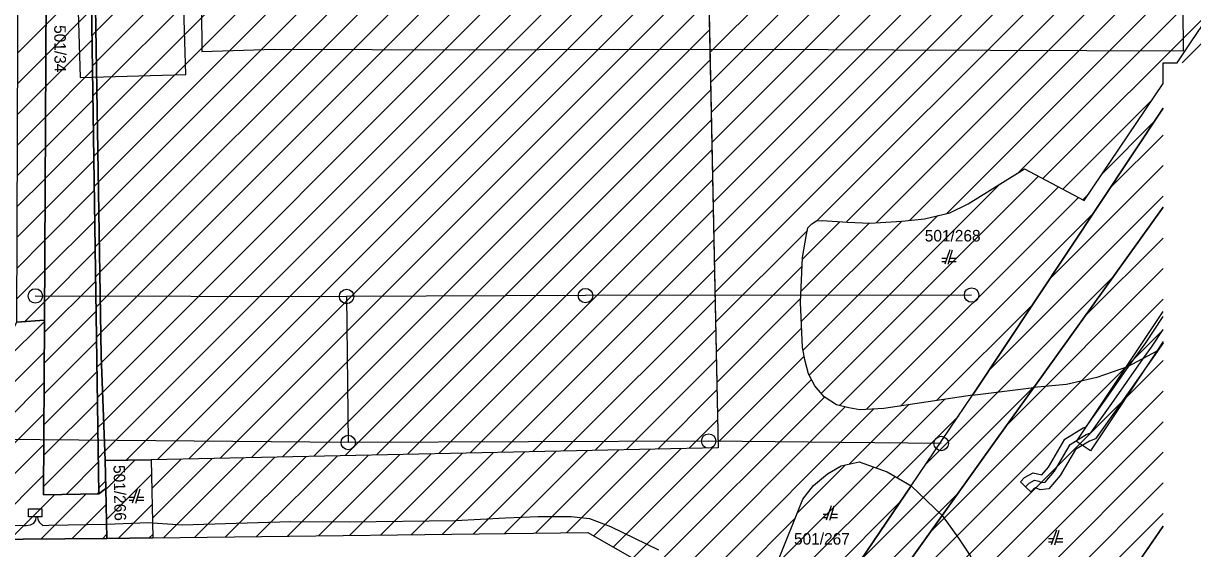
# Model space of a CAD drawing. Extents: x -264309 to -263505, y -1242443 to -1241763.
# Drawn here: x -263948.8 to -263786.7, y -1242319 to -1242246.2 of the extents above; entities that cross this region are included whole.
import ezdxf

# ---------------------------------------------------------------- set-up
doc = ezdxf.new("R2010")
doc.units = 0
for name, color, linetype in [('KFA_DAZDOVA_KANALIZACIA_retencna_nadrz', 7, 'Continuous'), ('KFA_DAZDOVA_KANALIZACIA_vetva_D', 7, 'Continuous'), ('KFA_DAZDOVA_KANALIZACIA_vetva_E', 7, 'Continuous'), ('KFA_SO_50-2_POZIARNY_VODOVOD_TRASA', 7, 'Continuous'), ('KN_2019_08_16', 7, 'Continuous'), ('KN_2019_08_16_KLADPAR', 7, 'Continuous'), ('KN_2019_08_16_ZAPPAR', 7, 'Continuous'), ('SRAFY_PARCELY', 7, 'Continuous')]:
    doc.layers.add(name, color=color, linetype=linetype)

msp = doc.modelspace()

# ---------------------------------------------------------------- linework, layer by layer
at = {"layer": 'KFA_DAZDOVA_KANALIZACIA_retencna_nadrz'}
msp.add_lwpolyline([(-263941.49, -1242235.46), (-263940.97, -1242253.75), (-263926.32, -1242253.31), (-263926.85, -1242235.04)], close=True, dxfattribs=at)
at = {"layer": 'KFA_DAZDOVA_KANALIZACIA_vetva_D'}
msp.add_lwpolyline([(-263821.59, -1242304.45), (-263853.82, -1242304.12), (-263903.79, -1242304.32), (-263951.83, -1242303.9), (-264004.17, -1242304.05), (-264044.82, -1242304.22), (-264095.21, -1242304.15), (-264105.62, -1242304.17)], dxfattribs=at)
for centre in [(-263853.82, -1242304.12), (-263903.79, -1242304.32), (-263821.59, -1242304.45)]:
    msp.add_circle(centre, 1, dxfattribs=at)
at = {"layer": 'KFA_DAZDOVA_KANALIZACIA_vetva_E'}
for p, q in [((-263947.17, -1242284.01), (-263904.01, -1242284.08)), ((-263904.01, -1242284.08), (-263903.79, -1242304.32))]:
    msp.add_line(p, q, dxfattribs=at)
msp.add_lwpolyline([(-263817.37, -1242283.88), (-263870.9, -1242283.96), (-263904.01, -1242284.08)], dxfattribs=at)
for centre in [(-263947.17, -1242284.01), (-263904.01, -1242284.08), (-263870.9, -1242283.96), (-263817.37, -1242283.88)]:
    msp.add_circle(centre, 1, dxfattribs=at)
at = {"layer": 'KFA_SO_50-2_POZIARNY_VODOVOD_TRASA'}
msp.add_lwpolyline([(-263924.93, -1242185.13), (-263924.15, -1242197.09), (-263924.3, -1242220.9), (-263924.1, -1242250.12), (-263913.99, -1242249.8), (-263886.91, -1242249.88), (-263867.71, -1242249.83), (-263837.26, -1242249.84), (-263828.16, -1242249.9), (-263787.99, -1242250.03), (-263788.2, -1242220.84), (-263788.2, -1242200.51), (-263788.09, -1242179.92), (-263788.06, -1242148.96), (-263787.92, -1242127.95), (-263787.95, -1242110.97), (-263788.13, -1242082.54), (-263828.43, -1242082.72), (-263836.78, -1242082.56), (-263867.31, -1242082.61), (-263886.71, -1242082.47), (-263924.08, -1242082.61), (-263924.64, -1242106.32), (-263924.48, -1242117.43)], close=True, dxfattribs=at)
at = {"layer": 'KN_2019_08_16'}
for p, q in [((-263795.99, -1242293.93), (-263790.83, -1242286.16)), ((-263795.99, -1242293.93), (-263790.83, -1242286.16)), ((-263790.83, -1242290.31), (-263791.71, -1242291.64)), ((-263790.83, -1242290.31), (-263791.71, -1242291.64)), ((-263791.71, -1242291.64), (-263800.9, -1242305.47)), ((-263791.71, -1242291.64), (-263800.9, -1242305.47)), ((-263802.81, -1242304.19), (-263795.99, -1242293.93)), ((-263802.81, -1242304.19), (-263795.99, -1242293.93)), ((-263800.9, -1242305.47), (-263802.81, -1242304.19)), ((-263800.9, -1242305.47), (-263802.81, -1242304.19))]:
    msp.add_line(p, q, dxfattribs=at)
for points in [[(-263790.83, -1242290.5), (-263791.59, -1242291.66), (-263797.1, -1242299.46), (-263800.21, -1242303.81), (-263801.03, -1242304.12), (-263802.98, -1242305.3), (-263805.07, -1242308.88), (-263806.66, -1242310.76), (-263807.87, -1242310.9), (-263808.52, -1242310.61), (-263808.8, -1242310.77), (-263809.16, -1242311.14), (-263809.88, -1242310.45), (-263810.6, -1242309.76), (-263810.02, -1242309.15), (-263808.82, -1242308.51), (-263807.62, -1242308.79), (-263806.71, -1242307.72), (-263804.46, -1242303.86), (-263801.91, -1242302.3), (-263801.47, -1242302.15), (-263798.74, -1242298.32), (-263795.58, -1242293.75), (-263793.23, -1242290.52), (-263790.83, -1242286.86)], [(-263809.88, -1242310.45), (-263809.41, -1242309.96), (-263808.67, -1242309.56), (-263808.06, -1242309.69), (-263807.69, -1242309.87), (-263807.17, -1242309.81), (-263805.89, -1242308.3), (-263803.72, -1242304.58), (-263801.47, -1242303.21), (-263800.84, -1242302.98), (-263797.92, -1242298.89), (-263793.53, -1242292.63), (-263792.41, -1242291.09), (-263790.83, -1242288.68)], [(-263954.68, -1242315.7), (-263948.7, -1242315.83), (-263948.46, -1242315.82), (-263947.86, -1242315.75), (-263947.37, -1242315.51), (-263947.08, -1242315.09), (-263947.04, -1242314.61)], [(-263946.86, -1242314.61), (-263946.83, -1242315.01), (-263946.58, -1242315.41), (-263946.15, -1242315.83), (-263945.29, -1242315.78), (-263937.31, -1242315.63), (-263931.52, -1242315.4), (-263930.92, -1242315.44), (-263926.77, -1242315.74), (-263919.34, -1242315.51), (-263911.76, -1242315.27), (-263903.58, -1242315.33), (-263888.93, -1242315.15), (-263882, -1242314.76), (-263877.47, -1242314.59), (-263872.88, -1242314.58), (-263870.34, -1242314.83), (-263867.42, -1242315.97), (-263860.78, -1242319.2)]]:
    msp.add_lwpolyline(points, dxfattribs=at)
msp.add_lwpolyline([(-263947.04, -1242314.61), (-263948.11, -1242314.61), (-263948.11, -1242313.51), (-263946.29, -1242313.51), (-263946.29, -1242314.61), (-263946.86, -1242314.61)], close=True, dxfattribs=at)
at = {"layer": 'KN_2019_08_16_KLADPAR'}
for p, q in [((-263786.91, -1242248.79), (-263758.42, -1242206.43)), ((-263788.88, -1242251.71), (-263786.91, -1242248.79)), ((-263801.77, -1242270.76), (-263790.83, -1242254.58)), ((-263790.83, -1242258), (-263817.23, -1242297.78)), ((-263817.83, -1242271.26), (-263810.05, -1242266.37)), ((-263810.05, -1242266.37), (-263801.77, -1242270.76)), ((-263823.91, -1242273.3), (-263820.38, -1242272.48)), ((-263820.38, -1242272.48), (-263817.83, -1242271.26)), ((-263840.06, -1242274.56), (-263839.51, -1242274)), ((-263839.51, -1242274), (-263838.86, -1242273.61)), ((-263838.86, -1242273.61), (-263838.09, -1242273.54)), ((-263838.09, -1242273.54), (-263834.58, -1242273.8)), ((-263834.58, -1242273.8), (-263831.48, -1242273.9)), ((-263831.48, -1242273.9), (-263827.03, -1242273.64)), ((-263827.03, -1242273.64), (-263823.91, -1242273.3)), ((-263840.83, -1242278.7), (-263840.26, -1242275.48)), ((-263840.26, -1242275.48), (-263840.06, -1242274.56)), ((-263841.11, -1242284.9), (-263840.83, -1242278.7)), ((-263820.82, -1242278.82), (-263821.5, -1242278.82)), ((-263820.4, -1242277.62), (-263821.1, -1242279.62)), ((-263820.6, -1242279.62), (-263820, -1242277.62)), ((-263819.5, -1242278.82), (-263820.36, -1242278.82)), ((-263821.5, -1242279.22), (-263820.96, -1242279.22)), ((-263820.48, -1242279.22), (-263819.5, -1242279.22)), ((-263840.8, -1242291.13), (-263841.11, -1242284.9)), ((-263840.43, -1242293.03), (-263840.8, -1242291.13)), ((-263839.99, -1242294.81), (-263840.43, -1242293.03)), ((-263839.09, -1242296.45), (-263839.99, -1242294.81)), ((-263837.8, -1242298.01), (-263839.09, -1242296.45)), ((-263836.1, -1242299.11), (-263837.8, -1242298.01)), ((-263817.23, -1242297.78), (-263829.54, -1242299.6)), ((-263834.37, -1242299.51), (-263836.1, -1242299.11)), ((-263832.88, -1242299.77), (-263834.37, -1242299.51)), ((-263829.54, -1242299.6), (-263832.88, -1242299.77)), ((-263933.04, -1242310.73), (-263933.74, -1242312.73)), ((-263933.24, -1242312.73), (-263932.64, -1242310.73)), ((-263933.46, -1242311.93), (-263934.14, -1242311.93)), ((-263934.14, -1242312.33), (-263933.6, -1242312.33)), ((-263933.12, -1242312.33), (-263932.14, -1242312.33)), ((-263932.14, -1242311.93), (-263933, -1242311.93)), ((-263837.26, -1242314.3), (-263837.94, -1242314.3)), ((-263836.84, -1242313.1), (-263837.54, -1242315.1)), ((-263837.04, -1242315.1), (-263836.44, -1242313.1)), ((-263835.94, -1242314.3), (-263836.8, -1242314.3)), ((-263837.94, -1242314.7), (-263837.4, -1242314.7)), ((-263836.92, -1242314.7), (-263835.94, -1242314.7)), ((-263796.96, -1242324.83), (-263790.83, -1242315.89)), ((-263806.04, -1242317.69), (-263806.72, -1242317.69)), ((-263805.62, -1242316.49), (-263806.32, -1242318.49)), ((-263805.82, -1242318.49), (-263805.22, -1242316.49)), ((-263804.72, -1242317.69), (-263805.58, -1242317.69)), ((-263806.72, -1242318.09), (-263806.18, -1242318.09)), ((-263805.7, -1242318.09), (-263804.72, -1242318.09))]:
    msp.add_line(p, q, dxfattribs=at)
for points in [[(-263945.92, -1242287.35), (-263949.74, -1242287.63), (-263949.41, -1242196.68), (-263949.38, -1242187.85), (-263949.49, -1242175.05), (-263949.55, -1242159.39), (-263950.14, -1242129.96), (-263950.48, -1242111.43), (-263955.8, -1242087.79), (-263956.24, -1242069.24), (-263949.96, -1242070.83), (-263947.13, -1242072.33), (-263942.68, -1242071.91), (-263941.47, -1242124.08), (-263944.59, -1242125.87), (-263946.11, -1242129.79), (-263945.51, -1242159.3), (-263945.41, -1242187.87)], [(-263945.92, -1242287.35), (-263945.41, -1242187.87), (-263945.51, -1242159.3), (-263946.11, -1242129.79), (-263944.59, -1242125.87), (-263941.47, -1242124.08), (-263940.13, -1242193.8), (-263938.35, -1242311.44), (-263946.05, -1242311.56)], [(-263939.79, -1242196.85), (-263933.6, -1242196.72), (-263889.52, -1242195.8), (-263854.81, -1242195.07), (-263852.5, -1242305.04), (-263931.11, -1242306.7), (-263937.48, -1242306.83), (-263938.02, -1242292.26), (-263938.87, -1242241.14), (-263939.37, -1242217.33)], [(-264045.86, -1242306.31), (-263951.37, -1242306.76), (-263951.29, -1242290.6), (-263949.74, -1242287.63), (-263945.92, -1242287.35), (-263946.05, -1242311.56), (-263938.35, -1242311.44), (-263937.4, -1242310.7), (-263937.27, -1242317.62), (-263989.58, -1242318.02), (-264012.87, -1242318.24), (-264024.87, -1242318.35), (-264045.81, -1242319.96), (-264048.82, -1242319.93), (-264044.28, -1242315.26), (-264044.13, -1242307.8)], [(-263937.27, -1242317.62), (-263937.4, -1242310.7), (-263937.48, -1242306.83), (-263931.11, -1242306.7), (-263930.87, -1242317.54)], [(-263843.11, -1242332.49), (-263836.94, -1242324.08), (-263844.32, -1242321.02), (-263840.75, -1242312.15), (-263839.31, -1242310.28), (-263837.34, -1242308.65), (-263835.46, -1242307.53), (-263832.97, -1242307.02), (-263829.09, -1242308.37), (-263825.74, -1242310.33), (-263842.23, -1242334.63), (-263842.59, -1242334.42)]]:
    msp.add_lwpolyline(points, close=True, dxfattribs=at)
for points in [[(-263942.54, -1242071.9), (-263941.18, -1242123.7), (-263940.74, -1242147.99), (-263940.34, -1242170.51), (-263939.79, -1242196.85), (-263939.37, -1242217.33), (-263938.87, -1242241.14), (-263938.02, -1242292.26), (-263937.48, -1242306.83), (-263937.4, -1242310.7), (-263938.35, -1242311.44), (-263940.13, -1242193.8), (-263941.47, -1242124.08), (-263942.68, -1242071.91)], [(-263915.82, -1242443.45), (-263899.7, -1242418.94), (-263895.05, -1242412.05), (-263870.81, -1242376.19), (-263864.8, -1242372.36), (-263866.24, -1242369.43), (-263842.59, -1242334.42), (-263842.23, -1242334.63), (-263825.74, -1242310.33), (-263817.23, -1242297.78), (-263790.83, -1242258)], [(-263889.11, -1242409.04), (-263871.85, -1242385.03), (-263844.47, -1242346.65), (-263821.45, -1242314.43), (-263813.84, -1242303.78), (-263808.74, -1242296.68), (-263790.83, -1242271.71)], [(-263790.83, -1242271.71), (-263808.74, -1242296.68), (-263813.84, -1242303.78), (-263821.45, -1242314.43), (-263844.47, -1242346.65), (-263871.85, -1242385.03), (-263889.11, -1242409.04)], [(-263790.83, -1242315.89), (-263796.96, -1242324.83), (-263799.93, -1242329.15), (-263801.69, -1242331.72)], [(-264069.25, -1242345.54), (-264061.99, -1242345.41), (-264045.98, -1242345.11), (-264024.64, -1242344.82), (-264024.87, -1242318.35), (-264012.87, -1242318.24), (-263989.58, -1242318.02), (-263937.27, -1242317.62), (-263930.87, -1242317.54), (-263870.55, -1242316.79)], [(-263870.55, -1242316.79), (-263843.11, -1242332.49), (-263842.59, -1242334.42), (-263866.24, -1242369.43), (-263870.81, -1242376.19), (-263895.05, -1242412.05), (-263899.7, -1242418.94), (-263928.14, -1242418.9), (-263933.06, -1242418.97), (-263955.09, -1242419.03), (-263978.33, -1242419.1), (-263997.04, -1242419.26), (-264025.44, -1242419.01), (-264068.96, -1242418.63), (-264069.2, -1242359.38), (-264069.25, -1242345.54)]]:
    msp.add_lwpolyline(points, dxfattribs=at)
at = {"layer": 'KN_2019_08_16_ZAPPAR'}
for p, q in [((-263817.23, -1242297.78), (-263808.74, -1242296.68)), ((-263825.74, -1242310.33), (-263821.45, -1242314.43))]:
    msp.add_line(p, q, dxfattribs=at)
for points in [[(-263790.83, -1242290.31), (-263791.71, -1242291.64), (-263795.77, -1242293.85), (-263800.03, -1242295.33), (-263804.21, -1242296.28), (-263808.74, -1242296.68)], [(-263821.45, -1242314.43), (-263819.18, -1242317.59), (-263817.51, -1242320.07), (-263816.33, -1242322.99), (-263815.74, -1242327.13)]]:
    msp.add_lwpolyline(points, dxfattribs=at)
at = {"layer": 'SRAFY_PARCELY'}
for p, q in [((-263853.65, -1242250.27), (-263766.58, -1242163.2)), ((-263853.56, -1242254.42), (-263766.58, -1242167.44)), ((-263853.48, -1242258.58), (-263766.58, -1242171.68)), ((-263853.39, -1242262.73), (-263766.58, -1242175.92)), ((-263853.3, -1242266.89), (-263766.58, -1242180.17)), ((-263853.21, -1242271.04), (-263766.58, -1242184.41)), ((-263853.13, -1242275.2), (-263766.58, -1242188.65)), ((-263853.04, -1242279.35), (-263766.58, -1242192.89)), ((-263938.77, -1242247.34), (-263887.18, -1242195.75)), ((-263938.7, -1242251.51), (-263882.84, -1242195.66)), ((-263938.63, -1242255.69), (-263878.51, -1242195.57)), ((-263938.56, -1242259.86), (-263874.18, -1242195.48)), ((-263938.49, -1242264.03), (-263869.84, -1242195.39)), ((-263938.42, -1242268.21), (-263865.51, -1242195.3)), ((-263938.35, -1242272.38), (-263861.18, -1242195.2)), ((-263938.28, -1242276.55), (-263856.84, -1242195.11)), ((-263854.81, -1242195.07), (-263852.5, -1242305.04)), ((-263938.21, -1242280.72), (-263854.76, -1242197.28)), ((-263852.95, -1242283.51), (-263766.58, -1242197.14)), ((-263838.81, -1242273.61), (-263766.36, -1242201.16)), ((-263938.14, -1242284.9), (-263854.68, -1242201.43)), ((-263834.75, -1242273.79), (-263763.81, -1242202.85)), ((-263938.07, -1242289.07), (-263854.59, -1242205.59)), ((-263830.56, -1242273.85), (-263761.26, -1242204.54)), ((-263826, -1242273.53), (-263758.71, -1242206.24)), ((-263786.91, -1242248.79), (-263758.42, -1242206.43)), ((-263937.98, -1242293.23), (-263854.5, -1242209.74)), ((-263937.83, -1242297.32), (-263854.41, -1242213.9)), ((-263937.68, -1242301.41), (-263854.33, -1242218.05)), ((-263820.81, -1242272.58), (-263766.14, -1242217.91)), ((-263937.53, -1242305.5), (-263854.24, -1242222.21)), ((-263934.56, -1242306.77), (-263854.15, -1242226.36)), ((-263930.23, -1242306.68), (-263854.07, -1242230.52)), ((-263810.88, -1242266.89), (-263774.86, -1242230.87)), ((-263925.89, -1242306.59), (-263853.98, -1242234.67)), ((-263921.56, -1242306.5), (-263853.89, -1242238.83)), ((-263945.71, -1242246.43), (-263939.43, -1242240.15)), ((-263917.22, -1242306.41), (-263853.8, -1242242.99)), ((-263945.73, -1242250.7), (-263939.37, -1242244.33)), ((-263807.48, -1242267.73), (-263783.57, -1242243.83)), ((-263949.6, -1242250.33), (-263945.71, -1242246.44)), ((-263939.31, -1242247.92), (-263938.77, -1242247.38)), ((-263912.89, -1242306.32), (-263853.72, -1242247.14)), ((-263788.16, -1242251.71), (-263783.68, -1242247.24)), ((-263945.75, -1242254.96), (-263939.3, -1242248.51)), ((-263788.88, -1242251.71), (-263786.91, -1242248.79)), ((-263949.62, -1242254.59), (-263945.73, -1242250.7)), ((-263908.56, -1242306.22), (-263853.63, -1242251.3)), ((-263945.78, -1242259.23), (-263939.24, -1242252.69)), ((-263939.25, -1242252.1), (-263938.7, -1242251.55)), ((-263790.83, -1242254.58), (-263790.83, -1242251.71)), ((-263790.83, -1242251.71), (-263788.88, -1242251.71)), ((-263801.77, -1242270.76), (-263790.83, -1242254.58)), ((-263949.64, -1242258.85), (-263945.75, -1242254.96)), ((-263939.18, -1242256.28), (-263938.63, -1242255.72)), ((-263904.22, -1242306.13), (-263853.54, -1242255.45)), ((-263945.8, -1242263.49), (-263939.18, -1242256.87)), ((-263804.71, -1242269.2), (-263792.38, -1242256.88)), ((-263949.65, -1242263.1), (-263945.78, -1242259.23)), ((-263945.82, -1242267.75), (-263939.11, -1242261.05)), ((-263939.12, -1242260.46), (-263938.56, -1242259.9)), ((-263899.89, -1242306.04), (-263853.45, -1242259.61)), ((-263799.28, -1242267.07), (-263792.05, -1242259.85)), ((-263798.15, -1242269.03), (-263790.83, -1242261.71)), ((-263949.67, -1242267.36), (-263945.8, -1242263.49)), ((-263939.06, -1242264.64), (-263938.49, -1242264.07)), ((-263895.55, -1242305.95), (-263853.37, -1242263.76)), ((-263945.84, -1242272.02), (-263939.05, -1242265.23)), ((-263806.52, -1242281.65), (-263790.83, -1242265.95)), ((-263838.21, -1242297.52), (-263808.1, -1242267.41)), ((-263817.83, -1242271.26), (-263810.05, -1242266.37)), ((-263810.05, -1242266.37), (-263801.77, -1242270.76)), ((-263949.68, -1242271.62), (-263945.82, -1242267.76)), ((-263938.99, -1242268.82), (-263938.42, -1242268.24)), ((-263891.22, -1242305.86), (-263853.28, -1242267.92)), ((-263839.9, -1242294.97), (-263813.42, -1242268.49)), ((-263835.66, -1242299.21), (-263805.32, -1242268.88)), ((-263945.86, -1242276.28), (-263938.99, -1242269.41)), ((-263831.93, -1242299.72), (-263802.55, -1242270.35)), ((-263814.9, -1242294.27), (-263790.83, -1242270.2)), ((-263801.93, -1242270.67), (-263801.25, -1242269.99)), ((-263949.7, -1242275.88), (-263945.84, -1242272.02)), ((-263938.93, -1242273), (-263938.35, -1242272.42)), ((-263886.89, -1242305.77), (-263853.19, -1242272.07)), ((-263827.22, -1242299.26), (-263800.43, -1242272.47)), ((-263823.91, -1242273.3), (-263820.38, -1242272.48)), ((-263820.38, -1242272.48), (-263817.83, -1242271.26)), ((-263790.89, -1242271.8), (-263790.83, -1242271.74)), ((-263945.89, -1242280.55), (-263938.92, -1242273.59)), ((-263841.04, -1242283.38), (-263831.56, -1242273.9)), ((-263840.98, -1242287.56), (-263827.06, -1242273.64)), ((-263840.84, -1242278.94), (-263835.62, -1242273.72)), ((-263840.72, -1242291.54), (-263822.04, -1242272.87)), ((-263840.06, -1242274.56), (-263839.51, -1242274)), ((-263839.51, -1242274), (-263838.86, -1242273.61)), ((-263838.86, -1242273.61), (-263838.09, -1242273.54)), ((-263838.09, -1242273.54), (-263834.58, -1242273.8)), ((-263834.58, -1242273.8), (-263831.48, -1242273.9)), ((-263831.48, -1242273.9), (-263827.03, -1242273.64)), ((-263827.03, -1242273.64), (-263823.91, -1242273.3)), ((-263852.86, -1242287.66), (-263840.14, -1242274.94)), ((-263840.83, -1242278.7), (-263840.26, -1242275.48)), ((-263840.26, -1242275.48), (-263840.06, -1242274.56)), ((-263949.71, -1242280.14), (-263945.86, -1242276.29)), ((-263938.87, -1242277.18), (-263938.28, -1242276.59)), ((-263882.55, -1242305.67), (-263853.11, -1242276.23)), ((-263801.67, -1242286.82), (-263790.83, -1242275.98)), ((-263945.91, -1242284.81), (-263938.86, -1242277.77)), ((-263841.11, -1242284.9), (-263840.83, -1242278.7)), ((-263949.73, -1242284.4), (-263945.89, -1242280.55)), ((-263878.22, -1242305.58), (-263853.02, -1242280.38)), ((-263852.78, -1242291.82), (-263840.89, -1242279.93)), ((-263812.46, -1242301.85), (-263790.83, -1242280.22)), ((-263945.93, -1242289.08), (-263938.8, -1242281.94)), ((-263938.81, -1242281.36), (-263938.21, -1242280.76)), ((-263823.68, -1242307.29), (-263797.75, -1242281.36)), ((-263948.64, -1242287.55), (-263945.91, -1242284.82)), ((-263938.74, -1242285.54), (-263938.14, -1242284.94)), ((-263873.88, -1242305.49), (-263852.93, -1242284.54)), ((-263852.69, -1242295.98), (-263841.09, -1242284.37)), ((-263840.8, -1242291.13), (-263841.11, -1242284.9)), ((-263823.1, -1242316.74), (-263790.83, -1242284.47)), ((-263822.24, -1242298.52), (-263808.8, -1242285.09)), ((-263945.95, -1242293.34), (-263938.73, -1242286.12)), ((-263951.3, -1242292.91), (-263945.92, -1242287.53)), ((-263869.55, -1242305.4), (-263852.84, -1242288.69)), ((-263852.6, -1242300.13), (-263840.93, -1242288.46)), ((-263833.72, -1242331.6), (-263790.83, -1242288.71)), ((-263945.98, -1242297.61), (-263938.67, -1242290.3)), ((-263938.68, -1242289.71), (-263938.07, -1242289.11)), ((-263951.32, -1242297.18), (-263945.94, -1242291.8)), ((-263840.43, -1242293.03), (-263840.8, -1242291.13)), ((-263938.62, -1242293.89), (-263937.98, -1242293.26)), ((-263865.21, -1242305.31), (-263852.76, -1242292.85)), ((-263852.52, -1242304.29), (-263840.57, -1242292.34)), ((-263844.33, -1242346.46), (-263790.83, -1242292.95)), ((-263839.99, -1242294.81), (-263840.43, -1242293.03)), ((-263946, -1242301.87), (-263938.61, -1242294.48)), ((-263839.09, -1242296.45), (-263839.99, -1242294.81)), ((-263951.34, -1242301.44), (-263945.97, -1242296.06)), ((-263864.33, -1242320.35), (-263839.57, -1242295.58)), ((-263837.8, -1242298.01), (-263839.09, -1242296.45)), ((-263832.63, -1242320.49), (-263808.52, -1242296.38)), ((-263938.55, -1242298.07), (-263937.83, -1242297.35)), ((-263861.64, -1242321.89), (-263837.77, -1242298.03)), ((-263860.88, -1242305.22), (-263852.67, -1242297.01)), ((-263841.17, -1242347.54), (-263790.83, -1242297.19)), ((-263836.1, -1242299.11), (-263837.8, -1242298.01)), ((-263830.61, -1242307.84), (-263821.13, -1242298.36)), ((-263817.23, -1242297.78), (-263829.54, -1242299.6)), ((-263825.74, -1242310.33), (-263817.23, -1242297.78)), ((-263817.26, -1242297.78), (-263817.18, -1242297.7)), ((-263946.02, -1242306.14), (-263938.54, -1242298.66)), ((-263858.94, -1242323.43), (-263834.89, -1242299.39)), ((-263856.24, -1242324.98), (-263830.93, -1242299.67)), ((-263834.37, -1242299.51), (-263836.1, -1242299.11)), ((-263832.88, -1242299.77), (-263834.37, -1242299.51)), ((-263834.31, -1242307.29), (-263826.11, -1242299.09)), ((-263829.54, -1242299.6), (-263832.88, -1242299.77)), ((-263951.36, -1242305.7), (-263945.99, -1242300.33)), ((-263938.49, -1242302.25), (-263937.68, -1242301.44)), ((-263856.55, -1242305.13), (-263852.58, -1242301.16)), ((-263836.93, -1242347.54), (-263790.83, -1242301.44)), ((-263827.71, -1242309.18), (-263819.16, -1242300.63)), ((-263946.04, -1242310.41), (-263938.48, -1242302.84)), ((-263959.21, -1242317.79), (-263946.01, -1242304.59)), ((-263938.43, -1242306.43), (-263937.53, -1242305.53)), ((-263852.5, -1242305.04), (-263931.11, -1242306.7)), ((-263930.93, -1242314.82), (-263922.63, -1242306.52)), ((-263929.39, -1242317.52), (-263918.3, -1242306.43)), ((-263925.1, -1242317.47), (-263913.96, -1242306.34)), ((-263920.8, -1242317.41), (-263909.63, -1242306.25)), ((-263916.5, -1242317.36), (-263905.3, -1242306.15)), ((-263912.21, -1242317.31), (-263900.96, -1242306.06)), ((-263907.91, -1242317.25), (-263896.63, -1242305.97)), ((-263903.61, -1242317.2), (-263892.29, -1242305.88)), ((-263899.32, -1242317.15), (-263887.96, -1242305.79)), ((-263895.02, -1242317.09), (-263883.63, -1242305.7)), ((-263890.73, -1242317.04), (-263879.29, -1242305.61)), ((-263886.43, -1242316.99), (-263874.96, -1242305.51)), ((-263882.13, -1242316.93), (-263870.62, -1242305.42)), ((-263877.84, -1242316.88), (-263866.29, -1242305.33)), ((-263873.54, -1242316.83), (-263861.95, -1242305.24)), ((-263869.73, -1242317.26), (-263857.62, -1242305.15)), ((-263867.03, -1242318.8), (-263853.29, -1242305.06)), ((-263832.68, -1242347.54), (-263790.83, -1242305.68)), ((-263942.91, -1242311.51), (-263938.42, -1242307.02)), ((-263937.4, -1242310.84), (-263933.31, -1242306.74)), ((-263931.11, -1242306.7), (-263930.87, -1242317.54)), ((-263931.02, -1242310.67), (-263926.97, -1242306.61)), ((-263844.26, -1242321.05), (-263830.94, -1242307.73)), ((-263841.52, -1242314.07), (-263834.86, -1242307.41)), ((-263837.34, -1242308.65), (-263835.46, -1242307.53)), ((-263835.46, -1242307.53), (-263832.97, -1242307.02)), ((-263832.97, -1242307.02), (-263829.09, -1242308.37)), ((-263954.93, -1242317.76), (-263946.04, -1242308.86)), ((-263938.36, -1242310.61), (-263937.42, -1242309.67)), ((-263937.32, -1242315), (-263931.06, -1242308.75)), ((-263841.26, -1242322.29), (-263827.98, -1242309.02)), ((-263839.31, -1242310.28), (-263837.34, -1242308.65)), ((-263829.09, -1242308.37), (-263825.74, -1242310.33)), ((-263938.6, -1242311.44), (-263938.35, -1242311.2)), ((-263841.59, -1242333.69), (-263819.24, -1242311.34)), ((-263840.75, -1242312.15), (-263839.31, -1242310.28)), ((-263828.44, -1242347.54), (-263790.83, -1242309.92)), ((-263950.65, -1242317.72), (-263944.47, -1242311.54)), ((-263946.38, -1242317.69), (-263940.16, -1242311.47)), ((-263942.1, -1242317.66), (-263937.36, -1242312.91)), ((-263935.68, -1242317.6), (-263930.97, -1242312.9)), ((-263844.32, -1242321.02), (-263840.75, -1242312.15)), ((-263838.26, -1242323.53), (-263827.19, -1242312.46)), ((-263824.2, -1242347.54), (-263790.83, -1242314.16)), ((-263853.54, -1242326.52), (-263841.82, -1242314.8)), ((-263937.83, -1242317.62), (-263937.28, -1242317.08)), ((-263931.38, -1242317.55), (-263930.88, -1242317.05)), ((-263930.87, -1242317.54), (-263870.55, -1242316.79)), ((-263870.55, -1242316.79), (-263843.11, -1242332.49))]:
    msp.add_line(p, q, dxfattribs=at)

# ---------------------------------------------------------------- texts
at = {"layer": 'KN_2019_08_16_KLADPAR'}
for s, rotation, p in [('501/34', 270.3788, (-263944.55, -1242246.48)), ('501/266', 271.2382, (-263936.34, -1242307.46))]:
    msp.add_text(s, height=1.6, rotation=rotation, dxfattribs=at).set_placement(p)
for s, p in [('501/268', (-263823.86, -1242276.46)), ('501/267', (-263841.99, -1242318.47))]:
    msp.add_text(s, height=1.6, dxfattribs=at).set_placement(p)

doc.saveas('drawing.dxf')
